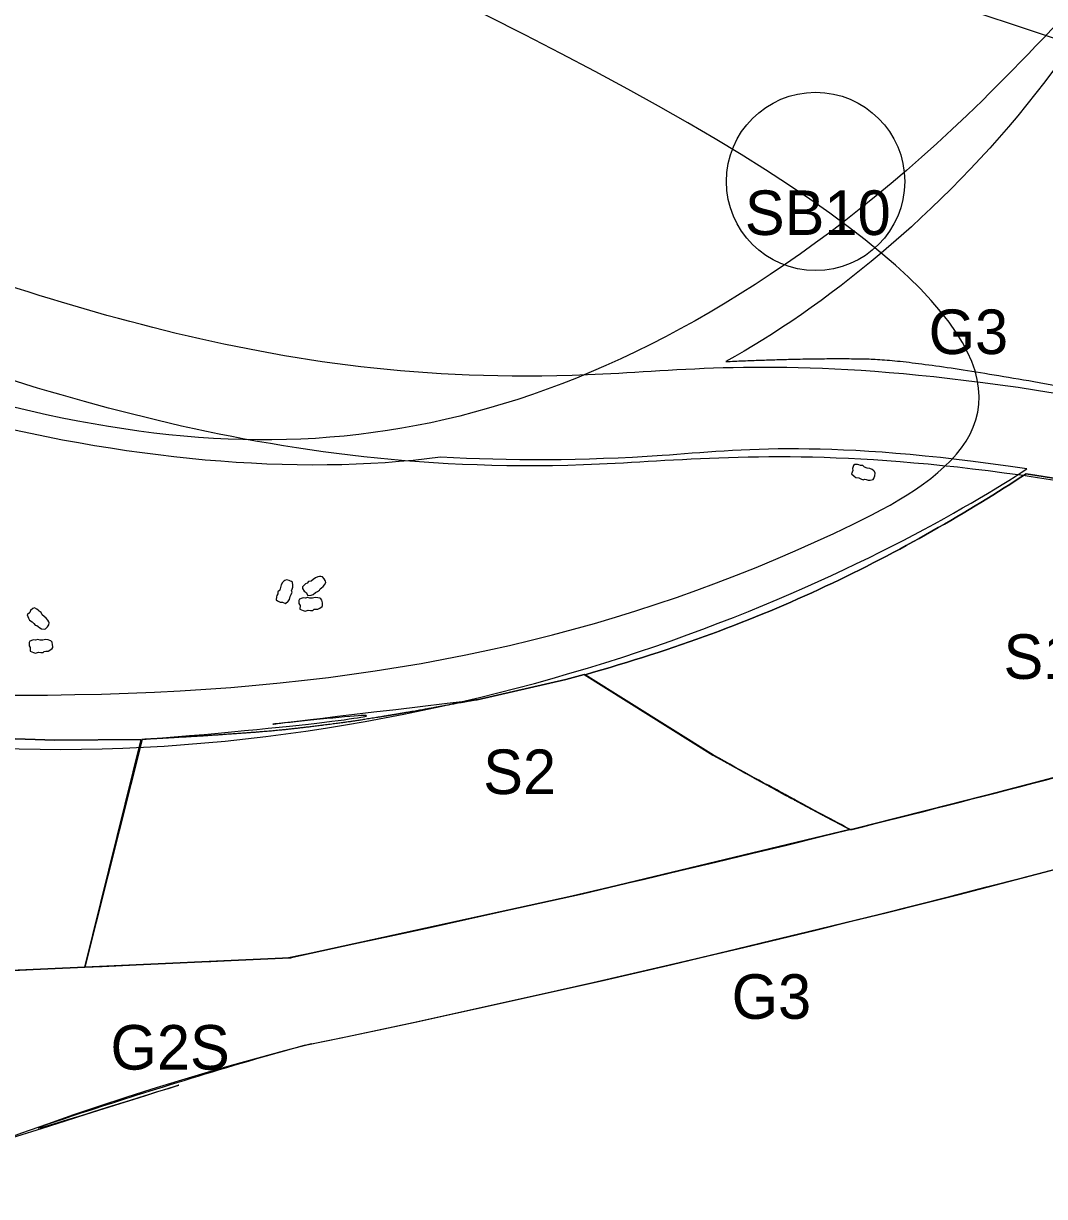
# Model space of a CAD drawing. Extents: x 0 to 512122, y 0 to 6212554.
# Drawn here: x 511570.06 to 511598.68, y 6211369.18 to 6211402.07 of the extents above; entities that cross this region are included whole.
import ezdxf

# ---------------------------------------------------------------- set-up
doc = ezdxf.new("R2010")
doc.units = 0
for name, color, linetype in [('_G3S_Slået græsser', 7, 'Continuous'), ('_Marksten', 7, 'Continuous'), ('_Paths', 7, 'Continuous'), ('_S1_rabarber', 7, 'Continuous'), ('_S2_skovjorbær', 7, 'Continuous'), ('_S3_Mynte', 7, 'Continuous'), ('_Spredmingskorridor', 7, 'Continuous'), ('_Spredmingskorridor_hatch', 7, 'Continuous'), ('TV_U_AFM_Symbl_Gul', 7, 'Continuous'), ('TV_U_LYS_Mastenummer', 7, 'Continuous')]:
    doc.layers.add(name, color=color, linetype=linetype)

msp = doc.modelspace()

# ---------------------------------------------------------------- linework, layer by layer
at = {"layer": '_G3S_Slået græsser'}
msp.add_open_spline([(511577.95, 6211373.42), (511575.884, 6211372.856), (511571.072, 6211371.35), (511569.062, 6211370.609), (511577.95, 6211373.42), (511569.062, 6211370.609)], degree=3, dxfattribs=at)
at = {"layer": '_Marksten'}
for points in [[(511593.267, 6211389.443), (511593.34, 6211389.375), (511593.388, 6211389.339), (511593.472, 6211389.331), (511593.533, 6211389.306), (511593.593, 6211389.281), (511593.636, 6211389.298), (511593.68, 6211389.286), (511593.739, 6211389.268), (511593.796, 6211389.271), (511593.873, 6211389.29), (511593.896, 6211389.316), (511593.905, 6211389.343), (511593.92, 6211389.385), (511593.93, 6211389.46), (511593.914, 6211389.506), (511593.891, 6211389.531), (511593.849, 6211389.564), (511593.785, 6211389.596), (511593.71, 6211389.608), (511593.635, 6211389.629), (511593.584, 6211389.677), (511593.521, 6211389.679), (511593.477, 6211389.699), (511593.438, 6211389.708), (511593.359, 6211389.708), (511593.326, 6211389.677), (511593.296, 6211389.597), (511593.303, 6211389.535)], [(511577.404, 6211385.809), (511577.476, 6211385.877), (511577.515, 6211385.923), (511577.528, 6211386.007), (511577.556, 6211386.065), (511577.585, 6211386.124), (511577.57, 6211386.168), (511577.586, 6211386.211), (511577.606, 6211386.27), (511577.608, 6211386.326), (511577.593, 6211386.404), (511577.568, 6211386.428), (511577.542, 6211386.439), (511577.501, 6211386.456), (511577.427, 6211386.471), (511577.379, 6211386.458), (511577.353, 6211386.437), (511577.318, 6211386.397), (511577.282, 6211386.335), (511577.265, 6211386.261), (511577.241, 6211386.187), (511577.19, 6211386.139), (511577.183, 6211386.076), (511577.161, 6211386.034), (511577.149, 6211385.995), (511577.144, 6211385.916), (511577.173, 6211385.882), (511577.252, 6211385.846), (511577.314, 6211385.85)], [(511578.023, 6211386.034), (511578.122, 6211386.046), (511578.18, 6211386.06), (511578.241, 6211386.119), (511578.299, 6211386.149), (511578.356, 6211386.179), (511578.371, 6211386.223), (511578.409, 6211386.249), (511578.461, 6211386.283), (511578.495, 6211386.328), (511578.53, 6211386.4), (511578.525, 6211386.434), (511578.51, 6211386.458), (511578.488, 6211386.496), (511578.437, 6211386.552), (511578.391, 6211386.57), (511578.357, 6211386.568), (511578.305, 6211386.557), (511578.24, 6211386.529), (511578.181, 6211386.479), (511578.118, 6211386.435), (511578.048, 6211386.427), (511578.005, 6211386.381), (511577.962, 6211386.36), (511577.93, 6211386.335), (511577.879, 6211386.275), (511577.882, 6211386.23), (511577.924, 6211386.155), (511577.976, 6211386.121)], [(511577.806, 6211385.651), (511577.898, 6211385.613), (511577.956, 6211385.596), (511578.038, 6211385.619), (511578.103, 6211385.617), (511578.168, 6211385.615), (511578.202, 6211385.646), (511578.248, 6211385.649), (511578.31, 6211385.654), (511578.362, 6211385.676), (511578.427, 6211385.722), (511578.439, 6211385.754), (511578.439, 6211385.783), (511578.437, 6211385.827), (511578.421, 6211385.901), (511578.389, 6211385.939), (511578.359, 6211385.954), (511578.308, 6211385.97), (511578.237, 6211385.977), (511578.162, 6211385.962), (511578.085, 6211385.955), (511578.02, 6211385.981), (511577.96, 6211385.962), (511577.912, 6211385.965), (511577.872, 6211385.959), (511577.798, 6211385.931), (511577.779, 6211385.891), (511577.779, 6211385.805), (511577.808, 6211385.75)], [(511570.163, 6211385.487), (511570.198, 6211385.394), (511570.226, 6211385.341), (511570.299, 6211385.297), (511570.342, 6211385.248), (511570.386, 6211385.199), (511570.432, 6211385.196), (511570.466, 6211385.165), (511570.512, 6211385.124), (511570.563, 6211385.101), (511570.642, 6211385.085), (511570.673, 6211385.098), (511570.693, 6211385.118), (511570.725, 6211385.15), (511570.767, 6211385.213), (511570.773, 6211385.262), (511570.763, 6211385.294), (511570.739, 6211385.342), (511570.696, 6211385.398), (511570.633, 6211385.443), (511570.575, 6211385.493), (511570.55, 6211385.559), (511570.494, 6211385.589), (511570.464, 6211385.626), (511570.432, 6211385.651), (511570.361, 6211385.686), (511570.318, 6211385.672), (511570.256, 6211385.613), (511570.236, 6211385.554)], [(511570.241, 6211384.472), (511570.333, 6211384.434), (511570.391, 6211384.417), (511570.473, 6211384.44), (511570.538, 6211384.438), (511570.603, 6211384.436), (511570.637, 6211384.467), (511570.683, 6211384.471), (511570.745, 6211384.476), (511570.797, 6211384.497), (511570.862, 6211384.543), (511570.874, 6211384.575), (511570.874, 6211384.604), (511570.872, 6211384.648), (511570.856, 6211384.722), (511570.824, 6211384.76), (511570.794, 6211384.775), (511570.743, 6211384.791), (511570.672, 6211384.798), (511570.597, 6211384.783), (511570.52, 6211384.776), (511570.455, 6211384.802), (511570.395, 6211384.783), (511570.348, 6211384.786), (511570.307, 6211384.78), (511570.233, 6211384.753), (511570.214, 6211384.712), (511570.214, 6211384.626), (511570.243, 6211384.571)]]:
    msp.add_lwpolyline(points, close=True, dxfattribs=at)
at = {"layer": '_Paths'}
for centre, radius, start, end in [((511490.629, 6211792.585), 425.663, 281.76765, 290.60954), ((511490.629, 6211792.585), 428.163, 281.76765, 290.60954), ((511492.968, 6211783.33), 418.626, 281.73735, 290.80486), ((511599.913, 6211288.279), 87.92, 104.34684, 136.49474)]:
    msp.add_arc(centre, radius, start, end, dxfattribs=at)
for points in [[(511619.187, 6211386.799), (511596.582, 6211393.479), (511585.389, 6211391.465), (511574.074, 6211393.08), (511564.353, 6211396.519), (511555.151, 6211400.37), (511543.395, 6211408.318), (511538.005, 6211417.069), (511534.527, 6211422.707), (511527.544, 6211428.597), (511520.899, 6211430.592), (511516.505, 6211433.059), (511513.01, 6211439.693), (511510.466, 6211444.112), (511507.781, 6211450.658), (511503.375, 6211454.994), (511500.203, 6211458.077), (511497.377, 6211464.569)], [(511614.911, 6211385.469), (511596.457, 6211390.915), (511585.439, 6211388.932), (511573.475, 6211390.64), (511563.453, 6211394.185), (511553.957, 6211398.16), (511541.549, 6211406.549), (511535.876, 6211415.757), (511532.609, 6211421.054), (511526.328, 6211426.352), (511519.916, 6211428.277), (511514.638, 6211431.24), (511510.82, 6211438.486), (511508.216, 6211443.009), (511505.662, 6211449.236), (511501.627, 6211453.206), (511498.108, 6211456.628), (511495.085, 6211463.571)], [(511496.284, 6211337.238), (511497.181, 6211337.983), (511503.211, 6211343.318), (511510.408, 6211356.244), (511526.967, 6211373.541), (511552.416, 6211374.723), (511569.62, 6211375.512), (511577.558, 6211375.876)]]:
    msp.add_open_spline(points, degree=3, dxfattribs=at)
at = {"layer": '_S1_rabarber'}
for p, q in [((511585.799, 6211383.811), (511589.403, 6211381.555)), ((511589.403, 6211381.555), (511585.8, 6211383.811)), ((511593.246, 6211379.466), (511593.245, 6211379.468)), ((511593.245, 6211379.468), (511593.246, 6211379.466))]:
    msp.add_line(p, q, dxfattribs=at)
msp.add_arc((511490.655, 6211792.581), 425.663, 283.9464, 286.97593, dxfattribs=at)
msp.add_arc((511490.655, 6211792.581), 425.663, 283.9464, 286.97593, dxfattribs=at)
for points, degree in [([(511585.799, 6211383.811), (511588.329, 6211384.532), (511592.644, 6211386.118), (511596.559, 6211388.394), (511598.166, 6211389.446)], 3), ([(511598.166, 6211389.446), (511596.559, 6211388.394), (511592.644, 6211386.118), (511588.329, 6211384.532), (511585.799, 6211383.811)], 3), ([(511598.166, 6211389.446), (511602.211, 6211388.829), (511607.308, 6211387.7), (511614.936, 6211385.465)], 2), ([(511614.936, 6211385.465), (511607.308, 6211387.7), (511602.211, 6211388.829), (511598.166, 6211389.446)], 2), ([(511593.245, 6211379.468), (511592.81, 6211379.697), (511591.52, 6211380.375), (511590.247, 6211381.084), (511589.403, 6211381.555)], 3), ([(511589.403, 6211381.555), (511590.247, 6211381.084), (511591.52, 6211380.375), (511592.81, 6211379.697), (511593.245, 6211379.468)], 3)]:
    msp.add_open_spline(points, degree=degree, dxfattribs=at)
at = {"layer": '_S2_skovjorbær'}
for points in [[(511582.777, 6211383.111), (511585.256, 6211383.681), (511585.773, 6211383.815), (511589.377, 6211381.558)], [(511589.377, 6211381.558), (511585.773, 6211383.815), (511585.256, 6211383.681), (511582.777, 6211383.111)], [(511593.219, 6211379.472), (511585.723, 6211377.669), (511577.518, 6211375.875), (511571.778, 6211375.611), (511573.379, 6211381.996)], [(511573.379, 6211381.996), (511571.778, 6211375.611), (511577.518, 6211375.875), (511585.723, 6211377.669), (511593.219, 6211379.472)]]:
    msp.add_lwpolyline(points, dxfattribs=at)
for points, degree in [([(511573.379, 6211381.996), (511578.378, 6211382.385), (511582.777, 6211383.111), (511573.379, 6211381.996), (511582.777, 6211383.111)], 3), ([(511582.557, 6211383.07), (511581.972, 6211382.962), (511581.387, 6211382.854), (511580.801, 6211382.752)], 2), ([(511582.777, 6211383.111), (511582.704, 6211383.097), (511582.631, 6211383.084), (511582.557, 6211383.07)], 2), ([(511580.142, 6211382.641), (511579.555, 6211382.545), (511578.967, 6211382.458), (511578.378, 6211382.385)], 2), ([(511580.581, 6211382.714), (511580.435, 6211382.689), (511580.288, 6211382.665), (511580.142, 6211382.641)], 2), ([(511580.801, 6211382.752), (511580.728, 6211382.739), (511580.655, 6211382.727), (511580.581, 6211382.714)], 2), ([(511578.378, 6211382.385), (511577.466, 6211382.272), (511576.551, 6211382.193), (511575.633, 6211382.13)], 2), ([(511574.381, 6211382.052), (511574.047, 6211382.032), (511573.713, 6211382.014), (511573.379, 6211381.996)], 2), ([(511575.633, 6211382.13), (511575.216, 6211382.101), (511574.799, 6211382.076), (511574.381, 6211382.052)], 2), ([(511589.377, 6211381.558), (511591.916, 6211380.161), (511593.219, 6211379.472), (511589.377, 6211381.558), (511593.219, 6211379.472)], 3), ([(511589.63, 6211381.417), (511589.546, 6211381.464), (511589.462, 6211381.511), (511589.377, 6211381.558)], 2), ([(511589.757, 6211381.347), (511589.715, 6211381.37), (511589.673, 6211381.394), (511589.63, 6211381.417)], 2), ([(511590.137, 6211381.135), (511590.01, 6211381.206), (511589.884, 6211381.276), (511589.757, 6211381.347)], 2), ([(511590.264, 6211381.065), (511590.221, 6211381.088), (511590.179, 6211381.112), (511590.137, 6211381.135)], 2), ([(511590.898, 6211380.715), (511590.686, 6211380.831), (511590.475, 6211380.948), (511590.264, 6211381.065)], 2), ([(511591.661, 6211380.299), (511591.406, 6211380.436), (511591.152, 6211380.575), (511590.898, 6211380.715)], 2), ([(511591.916, 6211380.161), (511591.831, 6211380.207), (511591.746, 6211380.253), (511591.661, 6211380.299)], 2), ([(511591.981, 6211380.126), (511591.959, 6211380.138), (511591.938, 6211380.15), (511591.916, 6211380.161)], 2), ([(511592.176, 6211380.022), (511592.111, 6211380.057), (511592.046, 6211380.092), (511591.981, 6211380.126)], 2), ([(511592.241, 6211379.988), (511592.219, 6211379.999), (511592.198, 6211380.011), (511592.176, 6211380.022)], 2), ([(511592.371, 6211379.919), (511592.328, 6211379.942), (511592.284, 6211379.965), (511592.241, 6211379.988)], 2), ([(511592.697, 6211379.746), (511592.588, 6211379.804), (511592.48, 6211379.861), (511592.371, 6211379.919)], 2), ([(511592.827, 6211379.678), (511592.784, 6211379.7), (511592.74, 6211379.723), (511592.697, 6211379.746)], 2), ([(511593.088, 6211379.54), (511593.001, 6211379.586), (511592.914, 6211379.632), (511592.827, 6211379.678)], 2), ([(511593.154, 6211379.506), (511593.132, 6211379.517), (511593.11, 6211379.529), (511593.088, 6211379.54)], 2), ([(511593.219, 6211379.472), (511593.197, 6211379.483), (511593.175, 6211379.494), (511593.154, 6211379.506)], 2)]:
    msp.add_open_spline(points, degree=degree, dxfattribs=at)
at = {"layer": '_S3_Mynte'}
msp.add_line((511571.776, 6211375.611), (511573.351, 6211381.998), dxfattribs=at)
msp.add_lwpolyline([(511573.351, 6211381.998), (511570.939, 6211381.975), (511567.316, 6211382.1), (511563.441, 6211382.432), (511559.802, 6211382.849), (511560.022, 6211379.806), (511560.059, 6211378.724), (511560.065, 6211377.836), (511560.047, 6211376.868), (511559.954, 6211375.075), (511571.776, 6211375.611)], dxfattribs=at)
msp.add_lwpolyline([(511571.776, 6211375.611), (511559.954, 6211375.075), (511560.047, 6211376.868), (511560.065, 6211377.836), (511560.059, 6211378.724), (511560.022, 6211379.806), (511559.802, 6211382.849), (511563.441, 6211382.432), (511567.316, 6211382.1), (511570.939, 6211381.975), (511573.351, 6211381.998)], close=True, dxfattribs=at)
at = {"layer": '_Spredmingskorridor'}
for points in [[(511618.625, 6211420.62), (511606.029, 6211410.569), (511596.93, 6211398.178), (511583.32, 6211390.017), (511570.813, 6211390.175), (511555.007, 6211396.479), (511539.801, 6211408.822), (511527.664, 6211423.862), (511513.195, 6211431.425), (511508.403, 6211440.656), (511501.753, 6211451.707), (511492.266, 6211459.065), (511618.625, 6211420.62), (511492.266, 6211459.065)], [(511446.919, 6211452.593), (511459.024, 6211449.612), (511483.052, 6211444.239), (511494.738, 6211426.247), (511517.996, 6211408.457), (511535.129, 6211387.296), (511545.806, 6211384.873), (511574.749, 6211382.071), (511593.151, 6211386.596), (511609.301, 6211398.194), (511446.919, 6211452.593), (511609.301, 6211398.194)]]:
    msp.add_open_spline(points, degree=3, dxfattribs=at)
at = {"layer": '_Spredmingskorridor_hatch'}
for points, degree in [([(511581.75, 6211389.913), (511577.7, 6211389.37), (511567.855, 6211390.317), (511554.005, 6211396.469), (511538.606, 6211407.597), (511530.73, 6211425.908), (511512.751, 6211428.394), (511508.404, 6211441.832), (511502.763, 6211452.312), (511495.709, 6211456.958), (511492.308, 6211459.197)], 3), ([(511467.291, 6211448.868), (511473.268, 6211448.326), (511486.519, 6211446.703), (511493.234, 6211420.769), (511520.952, 6211413.243), (511528.733, 6211386.924), (511552.285, 6211384.428), (511571.21, 6211380.366), (511589.487, 6211384.409), (511596.578, 6211388.532), (511598.184, 6211389.583)], 3), ([(511618.667, 6211420.753), (511614.103, 6211417.732), (511605.185, 6211411.829), (511599.082, 6211399.357), (511592.448, 6211394.075), (511589.741, 6211392.592)], 3), ([(511589.741, 6211392.592), (511592.135, 6211392.703), (511595.326, 6211392.63), (511601.01, 6211391.551)], 2), ([(511598.184, 6211389.583), (511592.53, 6211390.425), (511587.822, 6211389.798), (511583.658, 6211389.807), (511581.75, 6211389.913)], 3)]:
    msp.add_open_spline(points, degree=degree, dxfattribs=at)
at = {"layer": 'TV_U_LYS_Mastenummer'}
msp.add_circle((511592.261, 6211397.643), 2.5, dxfattribs=at)
msp.add_circle((511592.261, 6211397.643), 2.5, dxfattribs=at)

# ---------------------------------------------------------------- texts
at = {"layer": 'TV_U_AFM_Symbl_Gul'}
for s, p in [('SB10', (511590.279, 6211396.142)), ('G3', (511595.431, 6211392.803)), ('S1', (511597.53, 6211383.695)), ('S2', (511582.943, 6211380.465)), ('G3', (511589.909, 6211374.162)), ('G2S', (511572.494, 6211372.738))]:
    msp.add_text(s, height=1.25, dxfattribs=at).set_placement(p)

doc.saveas('drawing.dxf')
